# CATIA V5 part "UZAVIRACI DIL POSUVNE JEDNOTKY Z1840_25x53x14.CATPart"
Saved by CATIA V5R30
Part number: UZAVIRACI DIL POSUVNE JEDNOTKY VETSI
Bounding box of the stored display mesh (mm): x -71 to 0, y -50 to 0, z -26.5 to 26.5
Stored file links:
  C:\Users\ondra\Desktop\PŘÍLOHA P III\CATIA\UZAVIRACI DIL POSUVNE JEDNOTKY Z1840_25x53x14.CATPart
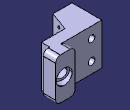
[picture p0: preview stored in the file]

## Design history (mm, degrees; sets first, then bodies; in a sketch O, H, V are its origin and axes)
Set1
  DatumSurface1 to DatumSurface50 "Z1840/25"
  Plane1: type Tangent, Support DatumSurface36, RefPoint vertex [face of DatumSurface32]
  Plane2: type Tangent, Support DatumSurface33, RefPoint vertex [face of DatumSurface36]
  Plane3: type Tangent, Support DatumSurface32, RefPoint vertex [face of DatumSurface32]
  Plane4: type Tangent, Support DatumSurface31, RefPoint vertex [face of DatumSurface31]
  Point1: type OnSurface, Support DatumSurface28, Length 0, Direction edge of DatumSurface29
  Plane5: type Tangent, Support DatumSurface28, RefPoint Point1
  Point2: type OnSurface, Support DatumSurface24, Length 0, Direction edge of DatumSurface23
  Plane6: type Tangent, Support DatumSurface24, RefPoint Point2
  Sketch1 on xy-plane, origin (0, 0, 0), H (1, 0, 0), V (0, 1, 0)
    reference projected curve E2 from face of DatumSurface51
    point P3 (-8.0456, -26.0589)
    line L1 (-8.0456, -26.0589) -> (0, -26.0589)
    line L2 (0, -26.0589) -> (0, -15.6388)
    line L3 (0, -15.6388) -> (-8.0456, -15.6388)
    line L4 (-8.0456, -15.6388) -> (-8.0456, -26.0589)
    point P5 (0, -15.6388)
    length L2 = 10.4201
    coincidence: P3 E2, P5 V, P5 E2
    horizontal: L1 H, L3 H
    vertical: L2 V, L4 V
  DatumCurve1
  DatumSurface51
  Join1: Elements (DatumSurface1; DatumSurface2; DatumSurface3; DatumSurface4; DatumSurface5; DatumSurface6; DatumSurface7; DatumSurface8; DatumSurface9; DatumSurface10; DatumSurface11; DatumSurface12; DatumSurface13; DatumSurface14; DatumSurface15; DatumSurface16; DatumSurface17; DatumSurface18; DatumSurface19; DatumSurface20; DatumSurface21; DatumSurface22; DatumSurface23; DatumSurface24; DatumSurface25; DatumSurface26; DatumSurface27; DatumSurface28; DatumSurface29; DatumSurface30; DatumSurface31; DatumSurface32; DatumSurface33; DatumSurface34; DatumSurface35; DatumSurface36; DatumSurface37; DatumSurface38; DatumSurface39; DatumSurface40; DatumSurface41; DatumSurface42; DatumSurface43; DatumSurface44; DatumSurface45; DatumSurface46; DatumSurface47; DatumSurface48; DatumSurface49; DatumSurface50)
Body1 (main body)
  CloseSurface1: CloseElement Join1
  Pocket1: profile Sketch1, direction (0, 0, -1), through (limit type 6), opposite side through (limit type 6)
